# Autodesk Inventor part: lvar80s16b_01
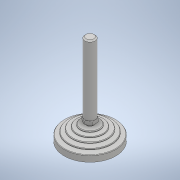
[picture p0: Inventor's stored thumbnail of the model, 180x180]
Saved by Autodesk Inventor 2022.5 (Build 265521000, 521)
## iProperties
Part Number: lvar80s16b_01
Material: 一般
Document SubType Name: Modeling
Designer: ImaoCorp
Density: 1 g/cm^3
Appearance: 既定
Author: ImaoCorp
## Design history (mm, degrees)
feature "lvar80s16b_01"
node "ソリッド1"
